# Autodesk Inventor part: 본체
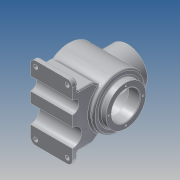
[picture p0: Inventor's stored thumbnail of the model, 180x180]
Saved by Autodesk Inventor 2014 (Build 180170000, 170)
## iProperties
Created: 2018-08
Part Number: 본체
Material: 알루미늄 6061
Document SubType Name: Modeling
Designer: kb542
Density: 2.71 g/cm^3
Appearance: 알루미늄 - 평지
Mass: 1886.05 g
Surface Area: 1087.48 cm^2
Volume: 695.96 cm^3
Author: kb542
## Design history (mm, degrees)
sketch "스케치1"
  geometry: L1 (0, 0)-(-120, 0); L2 (-120, 0)-(-120, 38); L3 (-120, 38)-(-108, 38); L4 (-108, 38)-(-108, 50); L5 (-108, 50)-(-11.329, 50); L6 (-17.837, 40)-(-98, 40); L7 (-98, 40)-(-98, 27); L8 (-98, 27)-(-120, 27); A1 r 116 centre (-116, 0) between (0, 0) and (-11.329, 50); A2 r 106 centre (-116, 0) between (-10, 0) and (-17.837, 40)
  constraints: 16 end point, 4 point on circle, 3 parallel, 3 point on line, 2 centre point, 2 perpendicular, 1 horizontal, 1 other
  dimensions: "d0" = 116 radius of A1; "d2" = 12 distance of L2.end L3.end; "d3" = 108 horizontal distance of L1.start L4.end; "d4" = 76 diameter of L3 L1; "d5" = 100 diameter of L5 L1; "d7" = 80 diameter of L6 L1; "d8" = 54 diameter of L8 L1; "d9" = 10 radial gap between concentric circles of A1 A2
revolve "회전1" sketch "스케치1" stored, may be unused: angle "d10" = 90 deg
node "작업 평면1"
sketch "스케치2"
  geometry: L1 (0, -50)-(0, -82); L2 (0, -82)-(-70, -82); L3 (-70, -82)-(-70, -72); L4 (-70, -72)-(-50, -72); L5 (-50, -72)-(-50, -43.437); L6 (-70, -72)-(-40.304, -29.59); L7 (70, -72)-(40.304, -29.59); L8 (50, -72)-(50, -43.437); L9 (70, -72)-(50, -72); L10 (70, -82)-(70, -72); L11 (0, -82)-(70, -82); A1 r 50 centre (0, 0) between (0, -50) and (-40.304, -29.59) reference; A2 r 12.5 centre (-27.5, -82) between (-15, -82) and (-40, -82); A3 r 17.5 centre (22.5, -82) between (40, -82) and (5, -82); 1 further point
  constraints: 22 end point, 8 point on line, 6 point on circle, 5 symmetric about line, 3 parallel, 2 centre point, 2 perpendicular, 1 vertical, 1 vertical alignment
  dimensions: "d12" = 82 distance from line of L2 point (0, 0); "d13" = 20 distance of L3.end L4.end; "d15" = 140 diameter of L3 L1; "d18" = 10 distance of L2.end L3.end; "d19" = 35 deg angle of L6 L3; "d20" = 12.5 radius of A2; "d21" = 17.5 radius of A3; "d22" = 27.5 distance of L1.end A2.centre; "d24" = 22.5 distance of A3.centre L1.end
extrude "돌출1" join sketch "스케치2" distance "d25" = 80; taper "d26" = 0 deg
sketch "스케치3"
  geometry: L1 (-70, -82)-(70, -82) reference; C1 r 12.5 at (-27.5, -82); C2 r 17.5 at (22.5, -82); A1 r 50 centre (0, 0) between (-40.304, -29.59) and (40.304, -29.59) reference
  constraints: 2 centre point, 2 point on line
  dimensions: "d27" = 27.5 horizontal distance of A1.centre C1.centre; "d28" = 22.5 horizontal distance of C2.centre A1.centre; "d29" = 12.5 radius of C1; "d30" = 17.5 radius of C2
extrude "돌출2" cut sketch "스케치3" stored distance "d31" = 80; taper "d32" = 0 deg
node "작업 평면2"
sketch "스케치4"
  geometry: L1 (-88, -120)-(-88, -20) reference; C1 r 38 at (-38, -70); 2 further points
  constraints: 1 centre point, 1 horizontal alignment, 1 midpoint
  dimensions: "d34" = 50 distance from line of C1.centre L1; "d35" = 76 diameter of C1
extrude "돌출3" join sketch "스케치4" stored distance "d36" = 80; taper "d37" = 0 deg
sketch "스케치5"
  geometry: C1 r 38 at (0, 0) reference; C2 r 27 at (0, 0); 1 further point
  constraints: 1 centre point, 1 coincident
  dimensions: "d38" = 54 diameter of C2
extrude "돌출4" cut sketch "스케치5" stored distance "d39" = 80; taper "d40" = 0 deg
sketch "스케치6"
  geometry: C1 r 27 at (0, 0) reference; 2 further points
  constraints: 1 vertical alignment
  dimensions: "d41" = 32.5 distance of C1.centre point (0, 32.5)
hole "구멍1" sketch "스케치6" at (0, 32.5) diameter "d42" = 3.242; stored, may be unused: countersink angle "d46" = 90 deg, drill point angle "d48" = 118 deg; dims "d43" = 8, "d44" = 4, "d45" = 2, "d47" = 10
sketch "스케치7"
  geometry: C1 r 27 at (0, 0) reference; 1 further point
  constraints: 1 vertical alignment
  dimensions: "d52" = 32.5 distance of C1.centre point (0, 32.5)
hole "구멍2" sketch "스케치7" at (0, 32.5) diameter "d53" = 3.242; stored, may be unused: countersink angle "d57" = 90 deg, drill point angle "d59" = 118 deg; dims "d54" = 8, "d55" = 4, "d56" = 2, "d58" = 10
fillet "모깎기1" dims "d63" = 10
sketch "스케치8"
  geometry: L1 (0, 110)-(0, 100) reference; L2 (80, 100)-(0, 100) reference; L3 (80, 100)-(80, 110) reference; L4 (70, 120)-(10, 120) reference; A1 r 10 centre (10, -10) between (0, -10) and (10, -20) reference; A2 r 10 centre (70, -10) between (70, -20) and (80, -10) reference; A3 r 10 centre (10, 110) between (10, 120) and (0, 110) reference; A4 r 10 centre (70, 110) between (80, 110) and (70, 120) reference; 5 further points
  constraints: 4 coincident
hole "구멍3" sketch "스케치8" at (10, 110), (70, 110), (70, -10), (10, -10) diameter "d64" = 8; stored, may be unused: countersink angle "d68" = 90 deg, drill point angle "d70" = 118 deg; dims "d65" = 8, "d66" = 4, "d67" = 2, "d69" = 10
fillet "모깎기2" dims "d71" = 3
chamfer "모따기1" distance "d72" = 1; stored, may be unused: second distance "d73" = 2, angle "d74" = 45 deg
fillet "모깎기3" dims "d75" = 3
node "작업 평면3"
sketch "스케치9"
  geometry: C1 r 32.5 at (0, 0); 1 further point
  constraints: 1 centre point, 1 coincident, 1 other
  dimensions: "d76" = 65 diameter of C1
feature "엠보싱1" sketch "스케치9" dims "d0" = 116, "d2" = 12, "d3" = 108, "d4" = 76, "d5" = 100, "d7" = 80, "d8" = 54, "d9" = 10, "d12" = 82, "d13" = 20, "d15" = 140, "d18" = 10, "d19" = 35 deg, "d20" = 12.5, "d21" = 17.5, "d22" = 27.5, "d24" = 22.5, "d77" = 0.5, "d78" = 0
node "솔리드1"
mirror "대칭1"
pattern_circular "원형 패턴1" dims angle "d50" = 360 deg
pattern_circular "원형 패턴2" dims angle "d61" = 360 deg
node "투영된 루프1"
other parameters: "d11" = -8, "d33" = -147
